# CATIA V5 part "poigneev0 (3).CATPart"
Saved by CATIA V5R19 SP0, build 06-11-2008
Part number: poignée
Bounding box of the stored display mesh (mm): x -12 to 12, y -60 to 70.732, z -207.048 to 250
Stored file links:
  G:\EU_thinkMotion\CFAO_2010\SIL_groupe2\SIL_groupe2\A reprendre\vfouquet\fouquet\poigneev0 (3).CATPart
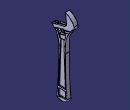
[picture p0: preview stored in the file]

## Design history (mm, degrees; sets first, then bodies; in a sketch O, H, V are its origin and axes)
Body1 (main body)
  Sketch1 on yz-plane, origin (0, 0, 0), H (0, 1, 0), V (0, 0, 1)
    arc A1 centre (-1.3509, -148.7994) radius 58.3095 from (-19.2939, -204.2796) to (18.9293, -203.4686) ccw
    spline S1 through (30, -200) (20, -40) (20, 40)
    spline S2 through (-30, -200) (-20, -40) (-20, 40)
    arc A2 centre (14.9217, -190.0544) radius 14 from (28.833, -188.4809) to (18.9293, -203.4686) cw
    arc A3 centre (-15.0102, -190.9511) radius 14 from (-19.2939, -204.2796) to (-28.9201, -189.3655) cw
    spline S3 through (20, 40) (20, 70) (20, 100) (28.833, 130) (60, 180)
    spline S4 through (60, 180) (70, 190) (70, 200)
    spline S5 through (70, 200) (60, 220) (40, 240) (20, 250)
    line L1 (20, 250) -> (28.833, 190)
    point P8 (20, 250)
    line L2 (28.833, 190) -> (14.9217, 176.6096)
    line L3 (14.9217, 176.6096) -> (-30, 165.6884)
    line L4 (-30, 165.6884) -> (-40, 163.2573)
    line L5 (-40, 163.2573) -> (-60, 158.3949)
    point P13 (-60, 158.3949)
    spline S6 through (-20, 40) (-24.6212, 100) (-60, 158.3949)
    line L6 (-30, 150) -> (10, 159.7246)
    line L7 (10, 159.7246) -> (17.2265, 130)
    line L8 (17.2265, 130) -> (-22.7735, 120.2754)
    line L9 (-22.7735, 120.2754) -> (-30, 150)
    point P18 (20, 40)
    point P19 (-20, 40)
    point P20 (20, 250)
    point P21 (20, 40)
    point P22 (-20, 40)
    point P23 (60, 180)
    point P24 (60, 180)
    point P25 (70, 200)
    point P26 (70, 200)
    point P27 (-60, 158.3949)
    radius A2 = 14
    radius A3 = 14
    coincidence: P20 P8, P18 P21, P19 P22, P23 P24, P25 P26, P13 P27
  Pad1: profile Sketch1, direction (1, 0, 0), length 12, mirrored extent
  Sketch2 on yz-plane, origin (0, 0, 0), H (0, 1, 0), V (0, 0, 1)
    line L1 (-20, -150) -> (20, -150)
    line L2 (20, -150) -> (20, -190)
    line L3 (20, -190) -> (-20, -190)
    line L4 (-20, -190) -> (-20, -150)
    line L5 (-20, -140) -> (20, -140)
    line L6 (20, -140) -> (10, 100)
    line L7 (10, 100) -> (-10, 100)
    line L8 (-10, 100) -> (-20, -140)
  Pocket1: profile Sketch2, direction along yz-plane, length 6, opposite side up to end face of Pad1
  RectPattern1: of Pocket1, direction 1 instances 2, spacing 18, along xy-plane reversed
  Sketch3 on {plane type Tangent, Support face of Pad1 from Sketch1.S6, RefPoint {point type OnSurface, Support face of Pad1 from Sketch1.S6, RefPoint {point stored without definition}, Length 0, Direction (0, -476.1379, 879.3706)}}, origin (-5.8482, -34.9284, 124.5928), H (1, 0, 0), V (0, 0.4761, -0.8794)
    point P1 (5.8482, -10)
    reference projected line E1 (-6.1518, -3.4842) -> (-6.1518, -16.3505) from edge [start face of Pad1 | face of Pad1 from Sketch1.S4]
    distance P1 E1 = 12
  Hole1: placed by Sketch3, at (0, -39.6898, 133.3865) direction (0, 0.9717, 0.2362), diameter 10, depth 65
  Sketch4 on {plane type Tangent, Support face of Pad1 from Sketch1.S6, RefPoint {point type OnSurface, Support face of Pad1 from Sketch1.S6, RefPoint {point stored without definition}, Length -9, Direction (0, -637.4379, 770.5017)}}, origin (-1.1136, -51.0131, 148.7402), H (1, 0, 0), V (0, 0.5927, -0.8054)
    point P1 (1.1136, 1.8973)
    reference projected line E1 (-10.8864, -13.1027) -> (-10.8864, 105.9627) from edge [start face of Pad1 | face of Pad1 from Sketch1.S6]
    reference projected line E2 (-10.8864, -13.1027) -> (13.1136, -13.1027) from edge [face of Pad1 from Sketch1.S6 | face of Pad1 from Sketch1.L5]
    distance P1 E1 = 12
    distance P1 E2 = 15
  Hole2: placed by Sketch4, at (0, -49.8886, 147.2121) direction (0, 0.9717, 0.2362), diameter 10, depth 100
  Sketch5 on zx-plane, origin (0, 0, 0), H (-1, 0, 0), V (0, 0, 1)
    line L1 (3, 162.3949) -> (3, 190)
    reference projected line E1 (12, 190) -> (12, 176.6096) from edge [start face of Pad1 | face of Pad1 from Sketch1.L2]
    line L2 (3, 190) -> (-3, 190)
    line L3 (-3, 190) -> (-3, 162.3949)
    line L4 (-3, 162.3949) -> (3, 162.3949)
    reference projected line E2 (-12, 190) -> (-12, 176.6096) from edge [face of Pad1 from Sketch1.L2 | end face of Pad1]
    reference projected line E3 (12, 158.3949) -> (-12, 158.3949) from edge [face of Pad1 from Sketch1.S6 | face of Pad1 from Sketch1.L5]
    distance E1 L1 = 9
    distance E2 L3 = 9
    distance L4 E3 = 4
  Pocket2: profile Sketch5, direction along edge [start face of Pad1 | face of Pad1 from Sketch1.L3], length 100, opposite side length 40
  Sketch6 on zx-plane, origin (0, 0, 0), H (-1, 0, 0), V (0, 0, 1)
    line L1 (-10, 140) -> (-10, 149.521)
    line L2 (-10, 149.521) -> (-12, 155)
    line L3 (-12, 155) -> (-20, 159.521)
    line L4 (-20, 159.521) -> (-20, 140)
    line L5 (-20, 140) -> (-10, 140)
    line L6 (10, 140) -> (10, 150.7148)
    line L7 (10, 150.7148) -> (12, 155)
    line L8 (12, 155) -> (20, 160.7148)
    line L9 (20, 160.7148) -> (20, 140)
    line L10 (20, 140) -> (10, 140)
  Pocket3: profile Sketch6, direction along edge [face of Pad1 from Sketch1.L3 | end face of Pad1], length 100, opposite side length 67
  Sketch7 on zx-plane, origin (0, 0, 0), H (-1, 0, 0), V (0, 0, 1)
    line L1 (-10, 140) -> (-9, 138)
    line L2 (-9, 138) -> (-11, 70)
    line L3 (-11, 70) -> (-12, -190)
    line L4 (-25.8845, 150) -> (-12, -190)
    line L5 (-10, 140) -> (-12, 140)
    line L6 (-12, 140) -> (-16.9483, 150)
    line L7 (-16.9483, 150) -> (-25.8845, 150)
    line L8 (10, 140) -> (12, 140)
    line L9 (12, 140) -> (15, 150)
    line L10 (15, 150) -> (25, 150)
    line L11 (25, 150) -> (20, 30)
    line L12 (20, 30) -> (12, -189.1016)
    line L13 (12, -189.1016) -> (11, 70)
    line L14 (11, 70) -> (9, 138)
    line L15 (9, 138) -> (10, 140)
  Pocket4: profile Sketch7, direction along edge [end face of Pad1 | face of Pad1 from Sketch1.L8] reversed, length 100, opposite side length 65
  Sketch8 on yz-plane, origin (0, 0, 0), H (0, 1, 0), V (0, 0, 1)
    point P1 (-10, 100)
    point P2 (-22, 120)
    line L1 (-22, 120) -> (18, 130)
    point P3 (18, 130)
    point P4 (10, 100)
    line L2 (10, 100) -> (-10, 100)
    spline S1 through (-22, 120) (18, 130) (10, 100)
    point P5 (18, 130)
    spline S2 through (10, 100) (-10, 100) (-22, 120)
    point P6 (-10, 100)
    point P7 (-22, 120)
    point P8 (10, 100)
    coincidence: P1 P6, P2 P7, P3 P5, P4 P8
  Pocket5: profile Sketch8, direction (-1, 0, 0), length -5, opposite side up to face of Pocket4 from Sketch7.L2
  Pocket6: profile Sketch8, direction (-1, 0, 0), length 5, opposite side up to face of Pocket4 from Sketch7.L14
